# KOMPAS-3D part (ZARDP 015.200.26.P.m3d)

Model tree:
1. Плоскость XY
2. Плоскость ZX
3. Плоскость ZY
4. Ось X
5. Ось Y
6. Ось Z
7. Начало координат
8. Булева операция:1
9. Булева операция:2
10. Булева операция:3
11. Булева операция:4
